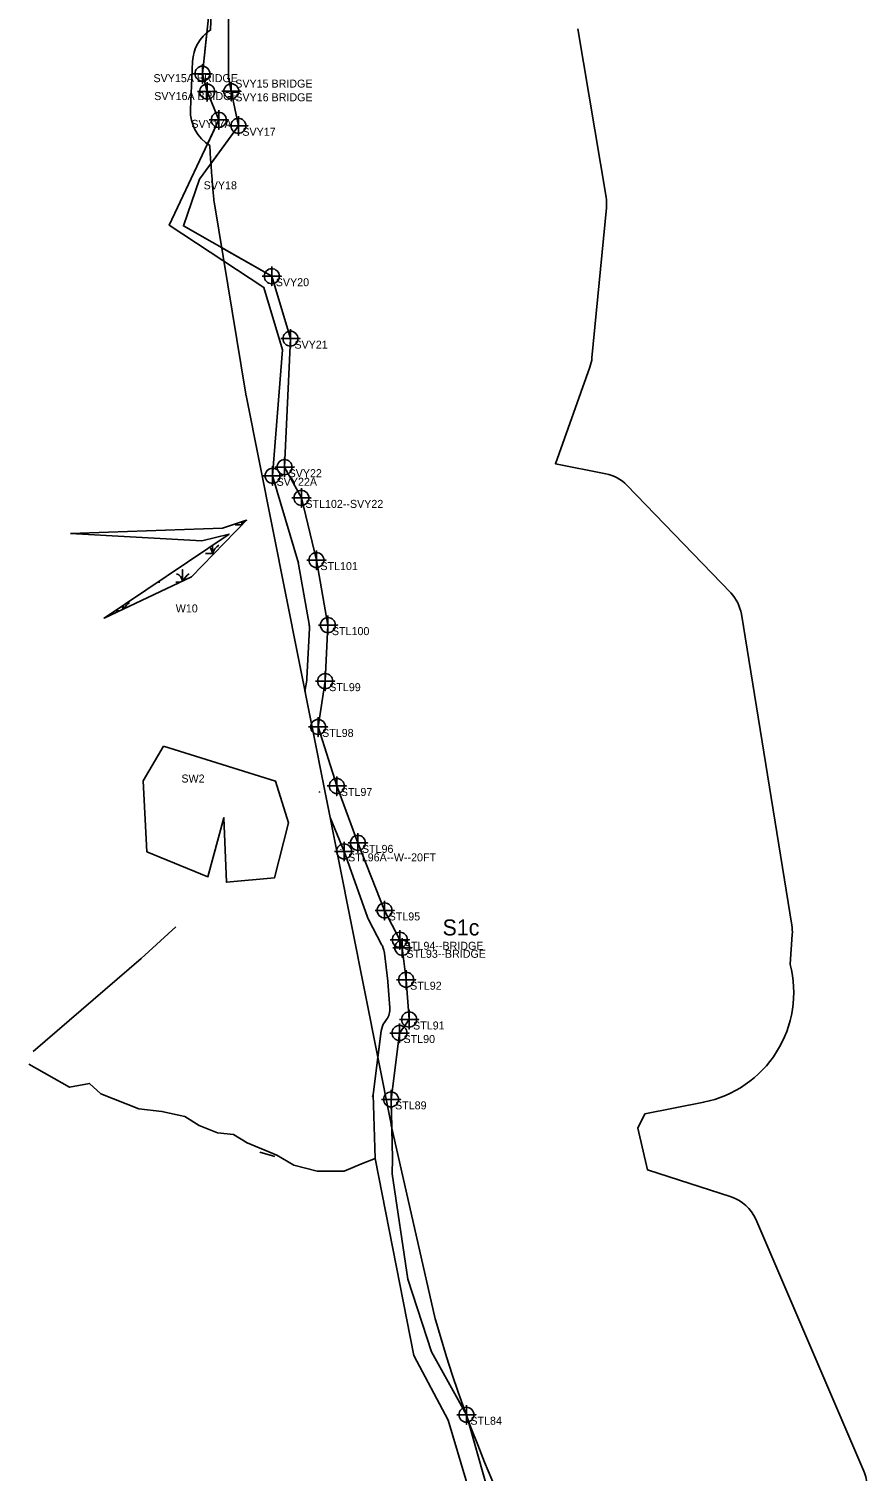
# Model space of a CAD drawing. Extents: x 1253697 to 1278588, y 912189 to 981699.
# Drawn here: x 1261754 to 1262802, y 925101 to 926903 of the extents above; entities that cross this region are included whole.
import ezdxf

# ---------------------------------------------------------------- set-up
doc = ezdxf.new("R2010")
doc.units = 0
for name, color, linetype in [('Default', 7, 'Continuous'), ('Exist Environmental Wetland Boundary', 7, 'Continuous'), ('Exist Hydro Jurisdictional Stream or Body of Water Mitigable', 7, 'Continuous'), ('Exist Hydro Jurisdictional Stream or Body of Water Mitigable Cogo Comment', 7, 'Continuous'), ('Exist Hydro Jurisdictional Stream or Body of Water Mitigable Cogo Number', 7, 'Continuous'), ('Exist Hydro Jurisdictional Stream or Body of Water Mitigable Cogo Point CELL', 7, 'Continuous')]:
    doc.layers.add(name, color=color, linetype=linetype)

msp = doc.modelspace()

# ---------------------------------------------------------------- linework, layer by layer
at = {"layer": 'Default'}
for p, q in [((1262475.6, 926692.8), (1262440.3, 926903.2)), ((1262475.6, 926692.8), (1262440.3, 926903.2)), ((1262475.6, 926692.8), (1262440.3, 926903.2)), ((1262475.6, 926692.8), (1262440.3, 926903.2)), ((1261958.6, 926862.3), (1261956, 926802.4)), ((1261958.6, 926862.3), (1261956, 926802.4)), ((1261958.6, 926862.3), (1261956, 926802.4)), ((1261958.6, 926862.3), (1261956, 926802.4)), ((1261985.7, 926687.2), (1262025.3, 926446.8)), ((1261985.7, 926687.2), (1262025.3, 926446.8)), ((1261985.7, 926687.2), (1262025.3, 926446.8)), ((1261985.7, 926687.2), (1262025.3, 926446.8)), ((1262458, 926492.3), (1262476.1, 926679.7)), ((1262458, 926492.3), (1262476.1, 926679.7)), ((1262458, 926492.3), (1262476.1, 926679.7)), ((1262458, 926492.3), (1262476.1, 926679.7)), ((1262025.6, 926445.2), (1262206.8, 925534.4)), ((1262025.6, 926445.2), (1262206.8, 925534.4)), ((1262025.6, 926445.2), (1262206.8, 925534.4)), ((1262025.6, 926445.2), (1262206.8, 925534.4)), ((1262631.5, 926198.3), (1262501.7, 926332.8)), ((1262631.5, 926198.3), (1262501.7, 926332.8)), ((1262631.5, 926198.3), (1262501.7, 926332.8)), ((1262631.5, 926198.3), (1262501.7, 926332.8)), ((1262707.9, 925783), (1262644.8, 926171.6)), ((1262707.9, 925783), (1262644.8, 926171.6)), ((1262707.9, 925783), (1262644.8, 926171.6)), ((1262707.9, 925783), (1262644.8, 926171.6)), ((1262705.9, 925734.3), (1262708.4, 925771.6)), ((1262705.9, 925734.3), (1262708.4, 925771.6)), ((1262705.9, 925734.3), (1262708.4, 925771.6)), ((1262705.9, 925734.3), (1262708.4, 925771.6)), ((1261889.1, 925551.9), (1261889.1, 925551.9)), ((1262207.1, 925533.1), (1262262.1, 925291.3)), ((1262207.1, 925533.1), (1262262.1, 925291.3)), ((1262207.1, 925533.1), (1262262.1, 925291.3)), ((1262207.1, 925533.1), (1262262.1, 925291.3)), ((1262061.6, 925494), (1262042.7, 925499.7)), ((1262798.1, 925100.9), (1262662.9, 925415.7)), ((1262798.1, 925100.9), (1262662.9, 925415.7)), ((1262798.1, 925100.9), (1262662.9, 925415.7)), ((1262798.1, 925100.9), (1262662.9, 925415.7))]:
    msp.add_line(p, q, dxfattribs=at)
for points in [[(1262475.4, 926347.2), (1262412.3, 926359.7), (1262455.4, 926480.3)], [(1262475.4, 926347.2), (1262412.3, 926359.7), (1262455.4, 926480.3)], [(1262475.4, 926347.2), (1262412.3, 926359.7), (1262455.4, 926480.3)], [(1262475.4, 926347.2), (1262412.3, 926359.7), (1262455.4, 926480.3)], [(1262632.2, 925443.6), (1262527.3, 925477.4), (1262515.4, 925529.6), (1262524, 925547.3), (1262597.7, 925561.9)], [(1262632.2, 925443.6), (1262527.3, 925477.4), (1262515.4, 925529.6), (1262524, 925547.3), (1262597.7, 925561.9)], [(1262632.2, 925443.6), (1262527.3, 925477.4), (1262515.4, 925529.6), (1262524, 925547.3), (1262597.7, 925561.9)], [(1262632.2, 925443.6), (1262527.3, 925477.4), (1262515.4, 925529.6), (1262524, 925547.3), (1262597.7, 925561.9)]]:
    msp.add_lwpolyline(points, dxfattribs=at)
for centre, radius, start, end in [((1263328.7, 926823.7), 1350, 169.1413, 176.6852), ((1263328.7, 926823.7), 1350, 169.1413, 176.6852), ((1263328.7, 926823.7), 1350, 169.1413, 176.6852), ((1263328.7, 926823.7), 1350, 169.1413, 176.6852), ((1262008.6, 926860.2), 50, 123.6033, 177.5192), ((1262008.6, 926860.2), 50, 123.6033, 177.5192), ((1262008.6, 926860.2), 50, 123.6033, 177.5192), ((1262008.6, 926860.2), 50, 123.6033, 177.5192), ((1262006, 926800.2), 50, 177.5192, 239.0708), ((1262006, 926800.2), 50, 177.5192, 239.0708), ((1262006, 926800.2), 50, 177.5192, 239.0708), ((1262006, 926800.2), 50, 177.5192, 239.0708), ((1263328.7, 926823.7), 1350, 182.82, 185.6694), ((1263328.7, 926823.7), 1350, 182.82, 185.6694), ((1263328.7, 926823.7), 1350, 182.82, 185.6694), ((1263328.7, 926823.7), 1350, 182.82, 185.6694), ((1262035, 926695.3), 50, 185.6694, 189.3565), ((1262035, 926695.3), 50, 185.6694, 189.3565), ((1262035, 926695.3), 50, 185.6694, 189.3565), ((1262035, 926695.3), 50, 185.6694, 189.3565), ((1262426.3, 926684.5), 50, 354.4983, 9.5192), ((1262426.3, 926684.5), 50, 354.4983, 9.5192), ((1262426.3, 926684.5), 50, 354.4983, 9.5192), ((1262426.3, 926684.5), 50, 354.4983, 9.5192), ((1262408.3, 926497.1), 50, 340.3631, 354.4983), ((1262408.3, 926497.1), 50, 340.3631, 354.4983), ((1262408.3, 926497.1), 50, 340.3631, 354.4983), ((1262408.3, 926497.1), 50, 340.3631, 354.4983), ((1262074.6, 926454.9), 50, 189.3565, 191.2557), ((1262074.6, 926454.9), 50, 189.3565, 191.2557), ((1262074.6, 926454.9), 50, 189.3565, 191.2557), ((1262074.6, 926454.9), 50, 189.3565, 191.2557), ((1262465.7, 926298.1), 50, 43.9614, 78.7674), ((1262465.7, 926298.1), 50, 43.9614, 78.7674), ((1262465.7, 926298.1), 50, 43.9614, 78.7674), ((1262465.7, 926298.1), 50, 43.9614, 78.7674), ((1262595.5, 926163.6), 50, 9.2234, 43.9614), ((1262595.5, 926163.6), 50, 9.2234, 43.9614), ((1262595.5, 926163.6), 50, 9.2234, 43.9614), ((1262595.5, 926163.6), 50, 9.2234, 43.9614), ((1262658.6, 925775), 50, 356.0583, 9.2234), ((1262658.6, 925775), 50, 356.0583, 9.2234), ((1262658.6, 925775), 50, 356.0583, 9.2234), ((1262658.6, 925775), 50, 356.0583, 9.2234), ((1262570.3, 925699.2), 140, 281.2557, 14.486), ((1262570.3, 925699.2), 140, 281.2557, 14.486), ((1262570.3, 925699.2), 140, 281.2557, 14.486), ((1262570.3, 925699.2), 140, 281.2557, 14.486), ((1262255.9, 925544.2), 50, 191.2557, 192.8081), ((1262255.9, 925544.2), 50, 191.2557, 192.8081), ((1262255.9, 925544.2), 50, 191.2557, 192.8081), ((1262255.9, 925544.2), 50, 191.2557, 192.8081), ((1262616.9, 925396), 50, 23.2408, 72.1608), ((1262616.9, 925396), 50, 23.2408, 72.1608), ((1262616.9, 925396), 50, 23.2408, 72.1608), ((1262616.9, 925396), 50, 23.2408, 72.1608), ((1262310.8, 925302.4), 50, 192.8081, 195.8394), ((1262310.8, 925302.4), 50, 192.8081, 195.8394), ((1262310.8, 925302.4), 50, 192.8081, 195.8394), ((1262310.8, 925302.4), 50, 192.8081, 195.8394), ((1263850.1, 925739.1), 1650, 195.8394, 221.7719), ((1263850.1, 925739.1), 1650, 195.8394, 221.7719), ((1263850.1, 925739.1), 1650, 195.8394, 221.7719), ((1263850.1, 925739.1), 1650, 195.8394, 221.7719), ((1262752.1, 925081.2), 50, 0.6306, 23.2408), ((1262752.1, 925081.2), 50, 0.6306, 23.2408), ((1262752.1, 925081.2), 50, 0.6306, 23.2408), ((1262752.1, 925081.2), 50, 0.6306, 23.2408)]:
    msp.add_arc(centre, radius, start, end, dxfattribs=at)
at = {"layer": 'Exist Environmental Wetland Boundary'}
for p, q in [((1262020.6, 926283.6), (1262020.6, 926287.4)), ((1262020.6, 926287.4), (1262020.6, 926283.6)), ((1262012, 926283.4), (1262020.5, 926283.4)), ((1261914.9, 926211.8), (1261917.6, 926211.8)), ((1261937.6, 926211.8), (1261943, 926211.8)), ((1261871.8, 926178.2), (1261871.8, 926182.9)), ((1261871.8, 926182.9), (1261871.8, 926178.2)), ((1261863.2, 926176.1), (1261867.4, 926176.1))]:
    msp.add_line(p, q, dxfattribs=at)
msp.add_lwpolyline([(1261806.2, 926272.4), (1261996, 926279.3), (1262026.1, 926289.2), (1261957.4, 926218.6), (1261848, 926166.9), (1262004.3, 926271.8), (1261970.2, 926263.6)], close=True, dxfattribs=at)
for points in [[(1261974.8, 926247.6), (1261983.4, 926247.6), (1261983.4, 926257.8)], [(1261983.4, 926257.8), (1261983.4, 926247.6), (1261985.6, 926247.6)], [(1261946.2, 926213.4), (1261946.2, 926227.6), (1261946.2, 926213.4)]]:
    msp.add_lwpolyline(points, dxfattribs=at)
for centre, radius, start, end in [((1262038.9, 926277.3), 19.2, 145.7711, 160.7433), ((1262008.4, 926282.5), 12.3, 4.9244, 21.9143), ((1261971.2, 926246.7), 12.3, 4.1403, 45.0082), ((1262001.7, 926241.6), 19.2, 122.1274, 161.6222), ((1261934, 926210.9), 12.3, 10.9018, 67.535), ((1261964.5, 926205.8), 19.2, 122.1274, 155.6176), ((1261859.6, 926175.2), 12.3, 13.4385, 31.9027), ((1261890.1, 926170), 19.2, 122.1274, 153.109)]:
    msp.add_arc(centre, radius, start, end, dxfattribs=at)
at = {"layer": 'Exist Hydro Jurisdictional Stream or Body of Water Mitigable'}
for p, q in [((1262090.9, 926235.4), (1262058.7, 926344.7)), ((1262104.4, 926159.2), (1262091.2, 926234.1)), ((1262101.7, 926091.6), (1262104.7, 926154.2)), ((1262099.2, 926075.1), (1262101.4, 926089.3)), ((1262148.1, 925875.4), (1262130.6, 925917.7)), ((1262195.5, 925758.1), (1262178.4, 925791)), ((1262197.8, 925752), (1262197.1, 925754.3)), ((1262202.8, 925713.3), (1262198.6, 925748.2)), ((1262205.3, 925679.8), (1262202.9, 925712.2)), ((1262198.7, 925661.6), (1262201.2, 925665.3)), ((1262190.3, 925617.5), (1262194.6, 925651.3))]:
    msp.add_line(p, q, dxfattribs=at)
for points in [[(1262112.7, 927450.9), (1261878.9, 927167.5), (1261883.5, 927087.1), (1261936.3, 927020.8), (1261962.9, 927043.4), (1261980.3, 927030.5), (1261988.7, 927011.6), (1261970.9, 926847.2)], [(1261981.6, 926734.7), (1262015.9, 926782.1), (1262007.1, 926825.2), (1262003.6, 926842.3), (1262004, 927014), (1261994.1, 927027.3)], [(1261977.2, 926759.3), (1261991.4, 926789.5), (1261976.9, 926824.8), (1261970.9, 926847.2), (1261976.5, 926898.5)], [(1262047.6, 926580.1), (1261929.5, 926657.7), (1261991.4, 926789.5)], [(1262015.9, 926782.1), (1261967.5, 926715.2), (1261947.3, 926656.9), (1262057.7, 926594.1)], [(1262073.7, 926355.5), (1262081, 926516.1), (1262057.7, 926594.1), (1261995.2, 926629.7)], [(1262058.7, 926344.7), (1262071, 926502.1), (1262047.6, 926580.1), (1261997.9, 926612.9)], [(1262207.6, 925530.8), (1262206.8, 925565.5), (1262217.4, 925648.4), (1262229.4, 925665.3), (1262225.7, 925715), (1262220.9, 925754.9), (1262217.8, 925764.9), (1262198.8, 925801.6), (1262165.4, 925886), (1262139, 925957.1), (1262115.6, 926030.9), (1262124.5, 926088.1), (1262127.9, 926158.1), (1262113.5, 926239.4), (1262094.7, 926317.1), (1262073.7, 926355.5)], [(1262207.6, 925530.8), (1262206.8, 925565.5), (1262217.4, 925648.4), (1262229.4, 925665.3), (1262225.7, 925715), (1262220.9, 925754.9), (1262217.8, 925764.9), (1262198.8, 925801.6), (1262165.4, 925886), (1262139, 925957.1), (1262115.6, 926030.9), (1262124.5, 926088.1), (1262127.9, 926158.1), (1262113.5, 926239.4), (1262094.7, 926317.1), (1262073.7, 926355.5)], [(1262177.4, 925793.2), (1262148.1, 925875.4)], [(1261937.8, 925781.2), (1261894.3, 925741.6), (1261759.3, 925625.1)], [(1262194.6, 925651.3), (1262184.4, 925571.5), (1262186.8, 925491.6), (1262235.2, 925245.3), (1262278.4, 925164.8), (1262306.1, 925070.7)], [(1262326.4, 925081.5), (1262301, 925171.4), (1262257.6, 925250.2), (1262227.6, 925340.9), (1262208.4, 925472.4), (1262208.6, 925491.6), (1262206.8, 925565.5), (1262217.4, 925648.4)], [(1262186.8, 925491.6), (1262170, 925485.1), (1262148.2, 925475.8), (1262114.6, 925475.6), (1262085.1, 925483.2), (1262064.2, 925495.8), (1262026.9, 925511.1), (1262010, 925521.6), (1261990, 925523.6), (1261966.7, 925532.7), (1261948.9, 925544.2), (1261920.4, 925550.5), (1261891.6, 925553.8), (1261843.9, 925572.2), (1261829.8, 925585.4), (1261804.8, 925580.6), (1261753.9, 925609.4)], [(1262301.3, 925170), (1262301, 925171.4), (1262300.6, 925172)], [(1262301.3, 925170), (1262301, 925171.4), (1262300.6, 925172)]]:
    msp.add_lwpolyline(points, dxfattribs=at)
msp.add_lwpolyline([(1261922.2, 926006.7), (1261896.9, 925963.5), (1261901.6, 925875), (1261977.9, 925843.7), (1261997.8, 925917.5), (1262001, 925836.9), (1262061.1, 925842.5), (1262078.8, 925911), (1262062.4, 925963)], close=True, dxfattribs=at)
for centre, radius, start, end in [((1262069.2, 926230.2), 22.3, 10.0437, 13.5919), ((1262082.4, 926155.3), 22.3, 357.1819, 10.0437), ((1262079.3, 926092.7), 22.3, 351.2196, 357.1819), ((1262139, 925957.1), 23, 197.5609, 200.3999), ((1262165.4, 925886), 23, 200.3999, 201.5479), ((1262198.8, 925801.6), 23, 201.5479, 207.4597), ((1262175.7, 925747.8), 22.3, 16.8437, 27.4597), ((1262176.4, 925745.5), 22.3, 6.941, 16.8437), ((1262180.6, 925710.6), 22.3, 4.1949, 6.941), ((1262183, 925678.2), 22.3, 324.7087, 4.1949), ((1262217.4, 925648.4), 23, 144.7087, 172.683), ((1262162.2, 925574.3), 22.3, 344.8936, 352.683)]:
    msp.add_arc(centre, radius, start, end, dxfattribs=at)
at = {"layer": 'Exist Hydro Jurisdictional Stream or Body of Water Mitigable Cogo Point CELL'}
for points in [[(1261970.9, 926859.2), (1261970.9, 926835.2), (1261970.9, 926847.2), (1261982.9, 926847.2), (1261958.9, 926847.2)], [(1261976.9, 926836.8), (1261976.9, 926812.8), (1261976.9, 926824.8), (1261988.9, 926824.8), (1261964.9, 926824.8)], [(1262007.1, 926837.2), (1262007.1, 926813.2), (1262007.1, 926825.2), (1262019.1, 926825.2), (1261995.1, 926825.2)], [(1261991.4, 926801.5), (1261991.4, 926777.5), (1261991.4, 926789.5), (1262003.4, 926789.5), (1261979.4, 926789.5)], [(1262015.9, 926794.1), (1262015.9, 926770.1), (1262015.9, 926782.1), (1262027.9, 926782.1), (1262003.9, 926782.1)], [(1262057.7, 926606.1), (1262057.7, 926582.1), (1262057.7, 926594.1), (1262069.7, 926594.1), (1262045.7, 926594.1)], [(1262081, 926528.1), (1262081, 926504.1), (1262081, 926516.1), (1262093, 926516.1), (1262069, 926516.1)], [(1262073.7, 926367.5), (1262073.7, 926343.5), (1262073.7, 926355.5), (1262085.7, 926355.5), (1262061.7, 926355.5)], [(1262058.7, 926356.7), (1262058.7, 926332.7), (1262058.7, 926344.7), (1262070.7, 926344.7), (1262046.7, 926344.7)], [(1262094.7, 926329.1), (1262094.7, 926305.1), (1262094.7, 926317.1), (1262106.7, 926317.1), (1262082.7, 926317.1)], [(1262113.5, 926251.4), (1262113.5, 926227.4), (1262113.5, 926239.4), (1262125.5, 926239.4), (1262101.5, 926239.4)], [(1262127.9, 926170.1), (1262127.9, 926146.1), (1262127.9, 926158.1), (1262139.9, 926158.1), (1262115.9, 926158.1)], [(1262124.5, 926100.1), (1262124.5, 926076.1), (1262124.5, 926088.1), (1262136.5, 926088.1), (1262112.5, 926088.1)], [(1262115.6, 926042.9), (1262115.6, 926018.9), (1262115.6, 926030.9), (1262127.6, 926030.9), (1262103.6, 926030.9)], [(1262139, 925969.1), (1262139, 925945.1), (1262139, 925957.1), (1262151, 925957.1), (1262127, 925957.1)], [(1262165.4, 925898), (1262165.4, 925874), (1262165.4, 925886), (1262177.4, 925886), (1262153.4, 925886)], [(1262148.1, 925887.4), (1262148.1, 925863.4), (1262148.1, 925875.4), (1262160.1, 925875.4), (1262136.1, 925875.4)], [(1262198.8, 925813.6), (1262198.8, 925789.6), (1262198.8, 925801.6), (1262210.8, 925801.6), (1262186.8, 925801.6)], [(1262217.8, 925776.9), (1262217.8, 925752.9), (1262217.8, 925764.9), (1262229.8, 925764.9), (1262205.8, 925764.9)], [(1262220.9, 925766.9), (1262220.9, 925742.9), (1262220.9, 925754.9), (1262232.9, 925754.9), (1262208.9, 925754.9)], [(1262225.7, 925727), (1262225.7, 925703), (1262225.7, 925715), (1262237.7, 925715), (1262213.7, 925715)], [(1262229.4, 925677.3), (1262229.4, 925653.3), (1262229.4, 925665.3), (1262241.4, 925665.3), (1262217.4, 925665.3)], [(1262217.4, 925660.4), (1262217.4, 925636.4), (1262217.4, 925648.4), (1262229.4, 925648.4), (1262205.4, 925648.4)], [(1262206.8, 925577.5), (1262206.8, 925553.5), (1262206.8, 925565.5), (1262218.8, 925565.5), (1262194.8, 925565.5)], [(1262301, 925183.4), (1262301, 925159.4), (1262301, 925171.4), (1262313, 925171.4), (1262289, 925171.4)]]:
    msp.add_lwpolyline(points, dxfattribs=at)
for centre in [(1261970.9, 926847.2), (1261976.9, 926824.8), (1262007.1, 926825.2), (1261991.4, 926789.5), (1262015.9, 926782.1), (1262057.7, 926594.1), (1262081, 926516.1), (1262073.7, 926355.5), (1262058.7, 926344.7), (1262094.7, 926317.1), (1262113.5, 926239.4), (1262127.9, 926158.1), (1262124.5, 926088.1), (1262115.6, 926030.9), (1262139, 925957.1), (1262165.4, 925886), (1262148.1, 925875.4), (1262198.8, 925801.6), (1262217.8, 925764.9), (1262220.9, 925754.9), (1262225.7, 925715), (1262229.4, 925665.3), (1262217.4, 925648.4), (1262206.8, 925565.5), (1262301, 925171.4)]:
    msp.add_circle(centre, 9.38, dxfattribs=at)

# ---------------------------------------------------------------- texts
at = {"layer": 'Exist Environmental Wetland Boundary'}
for s, p in [('W10', (1261937.6, 926174)), ('SW2', (1261944.7, 925961.4))]:
    msp.add_text(s, height=10, dxfattribs=at).set_placement(p)
at = {"layer": 'Exist Hydro Jurisdictional Stream or Body of Water Mitigable Cogo Comment'}
for s, p in [('SVY15A BRIDGE', (1261909.8, 926836.6)), ('SVY15 BRIDGE', (1262012, 926829.8)), ('SVY16A BRIDGE', (1261910.7, 926814.2)), ('SVY16 BRIDGE', (1262012.1, 926812.7)), ('SVY17A', (1261957.1, 926779.5)), ('SVY17', (1262020.9, 926769.6)), ('SVY18', (1261972.5, 926702.7)), ('SVY20', (1262062.7, 926581.6)), ('SVY21', (1262086, 926503.6)), ('SVY22A', (1262063.7, 926332.2)), ('SVY22', (1262078.7, 926343)), ('STL102--SVY22', (1262099.7, 926304.6)), ('STL101', (1262118.5, 926226.9)), ('STL100', (1262132.9, 926145.6)), ('STL99', (1262129.5, 926075.6)), ('STL98', (1262120.6, 926018.4)), ('STL97', (1262144, 925944.6)), ('STL96A--W--20FT', (1262153.1, 925862.9)), ('STL96', (1262170.4, 925873.5)), ('STL95', (1262203.8, 925789.1)), ('STL94--BRIDGE', (1262222.8, 925752.4)), ('STL93--BRIDGE', (1262225.9, 925742.4)), ('STL92', (1262230.7, 925702.5)), ('STL91', (1262234.4, 925652.8)), ('STL90', (1262222.4, 925635.9)), ('STL89', (1262211.8, 925553)), ('STL84', (1262306, 925158.9))]:
    msp.add_text(s, height=10, dxfattribs=at).set_placement(p)
at = {"layer": 'Exist Hydro Jurisdictional Stream or Body of Water Mitigable Cogo Number'}
msp.add_text('S1c', height=20, dxfattribs=at).set_placement((1262271.2, 925770.3))

doc.saveas('drawing.dxf')
